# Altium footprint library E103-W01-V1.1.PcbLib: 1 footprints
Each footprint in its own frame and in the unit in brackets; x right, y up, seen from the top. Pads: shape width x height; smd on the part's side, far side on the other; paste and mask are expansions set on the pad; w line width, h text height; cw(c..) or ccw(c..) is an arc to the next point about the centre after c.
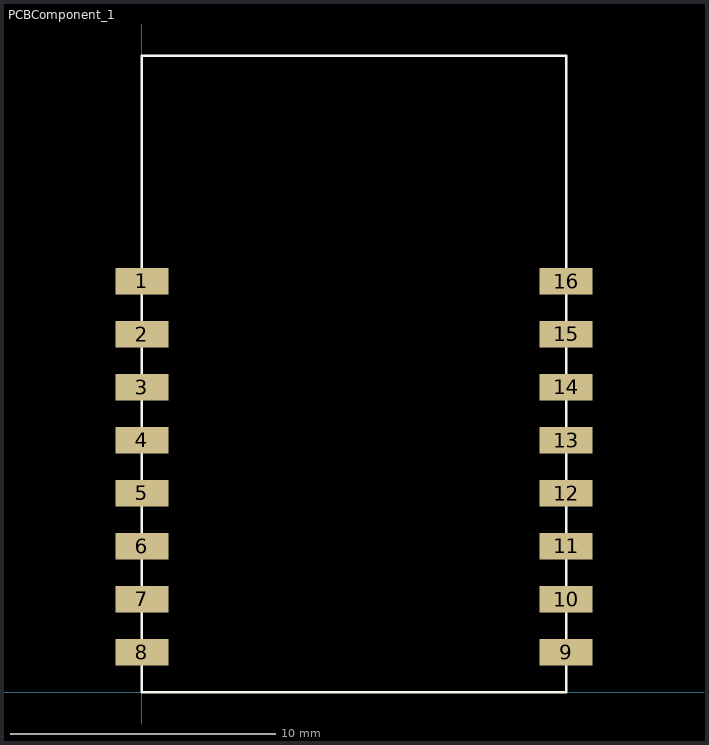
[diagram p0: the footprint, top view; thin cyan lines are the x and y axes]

## PCBComponent_1 [mm]
pads (16):
  rect 2x1 smd: 1(0,15.5) 2(0,13.5) 3(0,11.5) 4(0,9.5) 5(0,7.5) 6(0,5.5) 7(0,3.5) 8(0,1.5) 9(16,1.5) 10(16,3.5) 11(16,5.5) 12(16,7.5) 13(16,9.5) 14(16,11.5) 15(16,13.5) 16(16,15.5)
Top Overlay:
  lines w0.1: 0,0 0,24 16,24 16,0 0,0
